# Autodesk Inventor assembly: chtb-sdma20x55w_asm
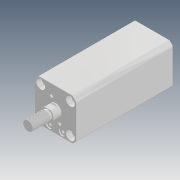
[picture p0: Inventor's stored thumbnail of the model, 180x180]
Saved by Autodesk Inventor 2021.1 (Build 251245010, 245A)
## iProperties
Company: Microsoft
Created: 2018-05
Part Number: chtb-sdma20x55w_asm
Description: STEP AP214
Document SubType Name: Assembly
Designer: user
Title: chtb-sdma20x55w_asm.STEP
Author: Windows
Revision Number: ÈÎºÎ
Sending System: SolidWorks 2015
Preprocessor: SwSTEP 2.0
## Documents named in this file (4)
- D:\Vault_2016\Projekty\Clamptek\Hydraulic\CHTB\CHTB-20\Inventor\CHTB-SDMA20x55W\chtb-sdma20x55w_asm.iam
- D:\Vault_2016\Projekty\Clamptek\Hydraulic\CHTB\CHTB-20\Inventor\CHTB-SDMA20x55W\CHTB-SDMA20X55NBT.ipt
- D:\Vault_2016\Projekty\Clamptek\Hydraulic\CHTB\CHTB-20\Inventor\CHTB-SDMA20x55W\CHTB-SDMA20X55WHSG.ipt
- D:\Vault_2016\Projekty\Clamptek\Hydraulic\CHTB\CHTB-20\Inventor\CHTB-SDMA20x55W\QG_3.ipt
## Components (3 placed, 3 different names)
1. CHTB-SDMA20X55NBT_1
2. CHTB-SDMA20X55WHSG_2
3. QG_3_3
